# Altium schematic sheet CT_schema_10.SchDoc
size 391 x 238 mm
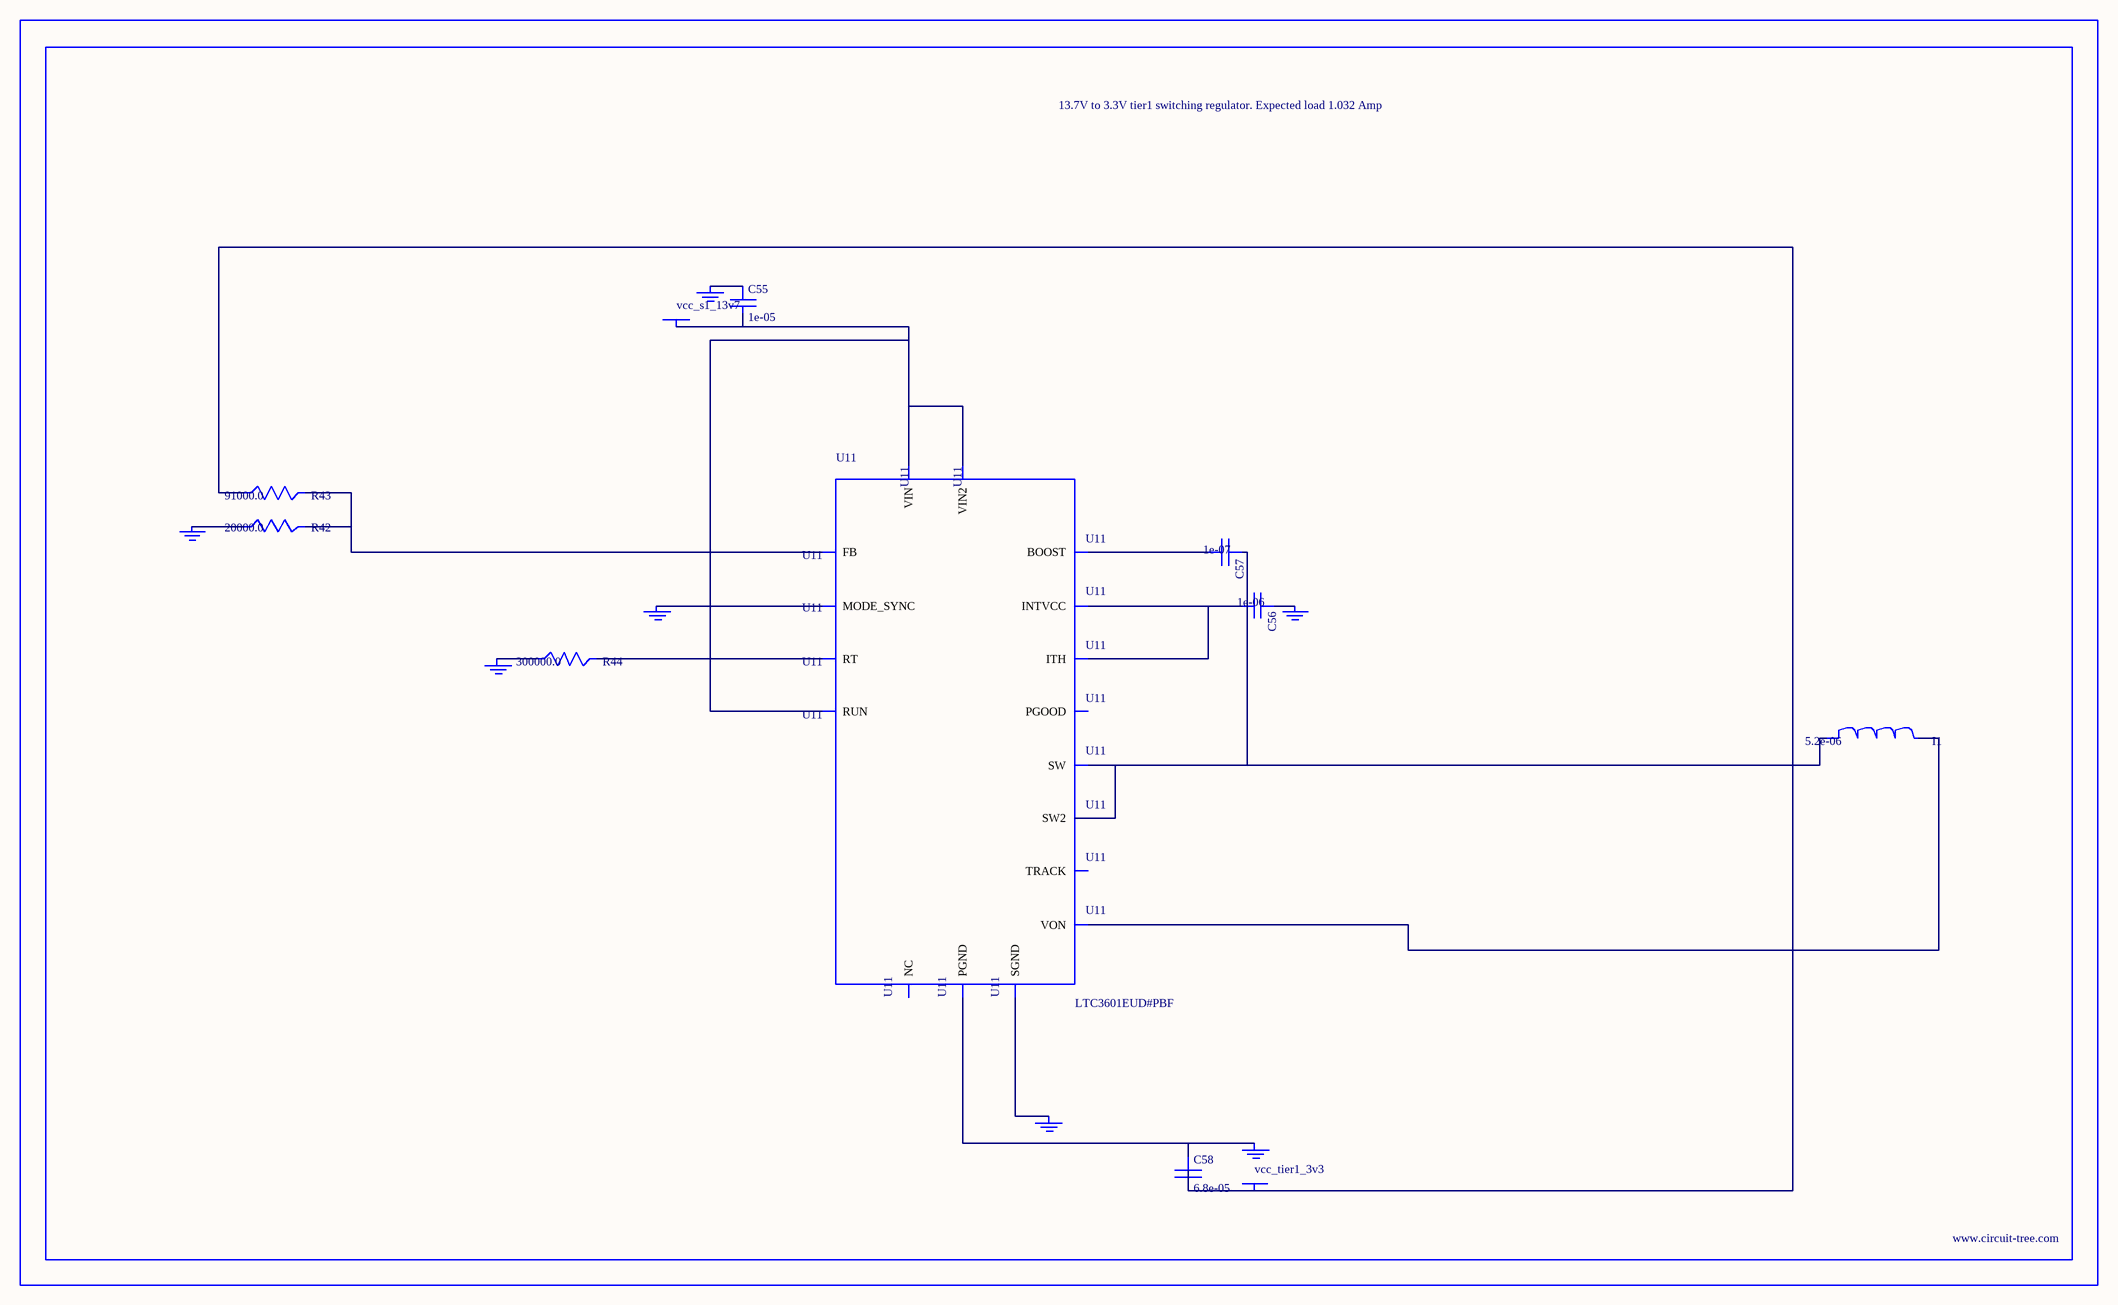
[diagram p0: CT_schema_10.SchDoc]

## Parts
BORDER9  (no value)
C55  1e-05  [C0805]
C56  1e-06  [C0603]
C57  1e-07  [C0402]
C58  6.8e-05  [2220]
GND_INSTANCE_9_0  (no value)
GND_INSTANCE_9_1  (no value)
GND_INSTANCE_9_2  (no value)
GND_INSTANCE_9_3  (no value)
GND_INSTANCE_9_4  (no value)
GND_INSTANCE_9_5  (no value)
GND_INSTANCE_9_6  (no value)
I1  5.2e-06  [DR1040]
POWER_INSTANCE_9_0  vcc_s1_13v7
POWER_INSTANCE_9_1  vcc_tier1_3v3
R42  20000.0  [R0603]
R43  91000.0  [R0603]
R44  300000.0  [R0603]
U11  LTC3601EUD#PBF  [QFN-16_EP]

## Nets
NetC55_1: C55.1 GND_INSTANCE_9_5.0(GND)
NetC55_2: C55.2 POWER_INSTANCE_9_0.0(PWR) U11.14(RUN) U11.15(VIN) U11.16(VIN2)
NetC56_1: C56.1 GND_INSTANCE_9_1.0(GND)
NetC56_2: C56.2 U11.7(INTVCC) U11.12(ITH)
NetC57_1: C57.1 I1.1 U11.3(SW) U11.4(SW2)
NetC57_2: C57.2 U11.6(BOOST)
NetC58_1: C58.1 GND_INSTANCE_9_6.0(GND) U11.17(PGND)
NetC58_2: C58.2 I1.2 POWER_INSTANCE_9_1.0(PWR) R43.1 U11.8(VON)
NetGND_INSTANCE_9_0_0: GND_INSTANCE_9_0.0(GND) U11.1(MODE_SYNC)
NetGND_INSTANCE_9_2_0: GND_INSTANCE_9_2.0(GND) U11.9(SGND)
NetGND_INSTANCE_9_3_0: GND_INSTANCE_9_3.0(GND) R44.1
NetGND_INSTANCE_9_4_0: GND_INSTANCE_9_4.0(GND) R42.1
NetR42_2: R42.2 R43.2 U11.11(FB)
NetR44_2: R44.2 U11.10(RT)

Not connected (* = marked no-connect by the designer): U11 2(PGOOD) 5(NC) 13(TRACK)

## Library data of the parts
BORDER9 = BORDER_PAGE9
C55 = C0805C106K8RACTU
C56 = C0603C105K3RACTU
C57 = C0402C104K3RACTU
C58 = C5750X5R1A686M
GND_INSTANCE_9_0-GND_INSTANCE_9_6 = GND
I1 = DR1040-5R2-R
POWER_INSTANCE_9_0 POWER_INSTANCE_9_1 = PWR
R42 = RC0603JR-0720KL
R43 = RC0603JR-0791KL
R44 = RC0603JR-07300KL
